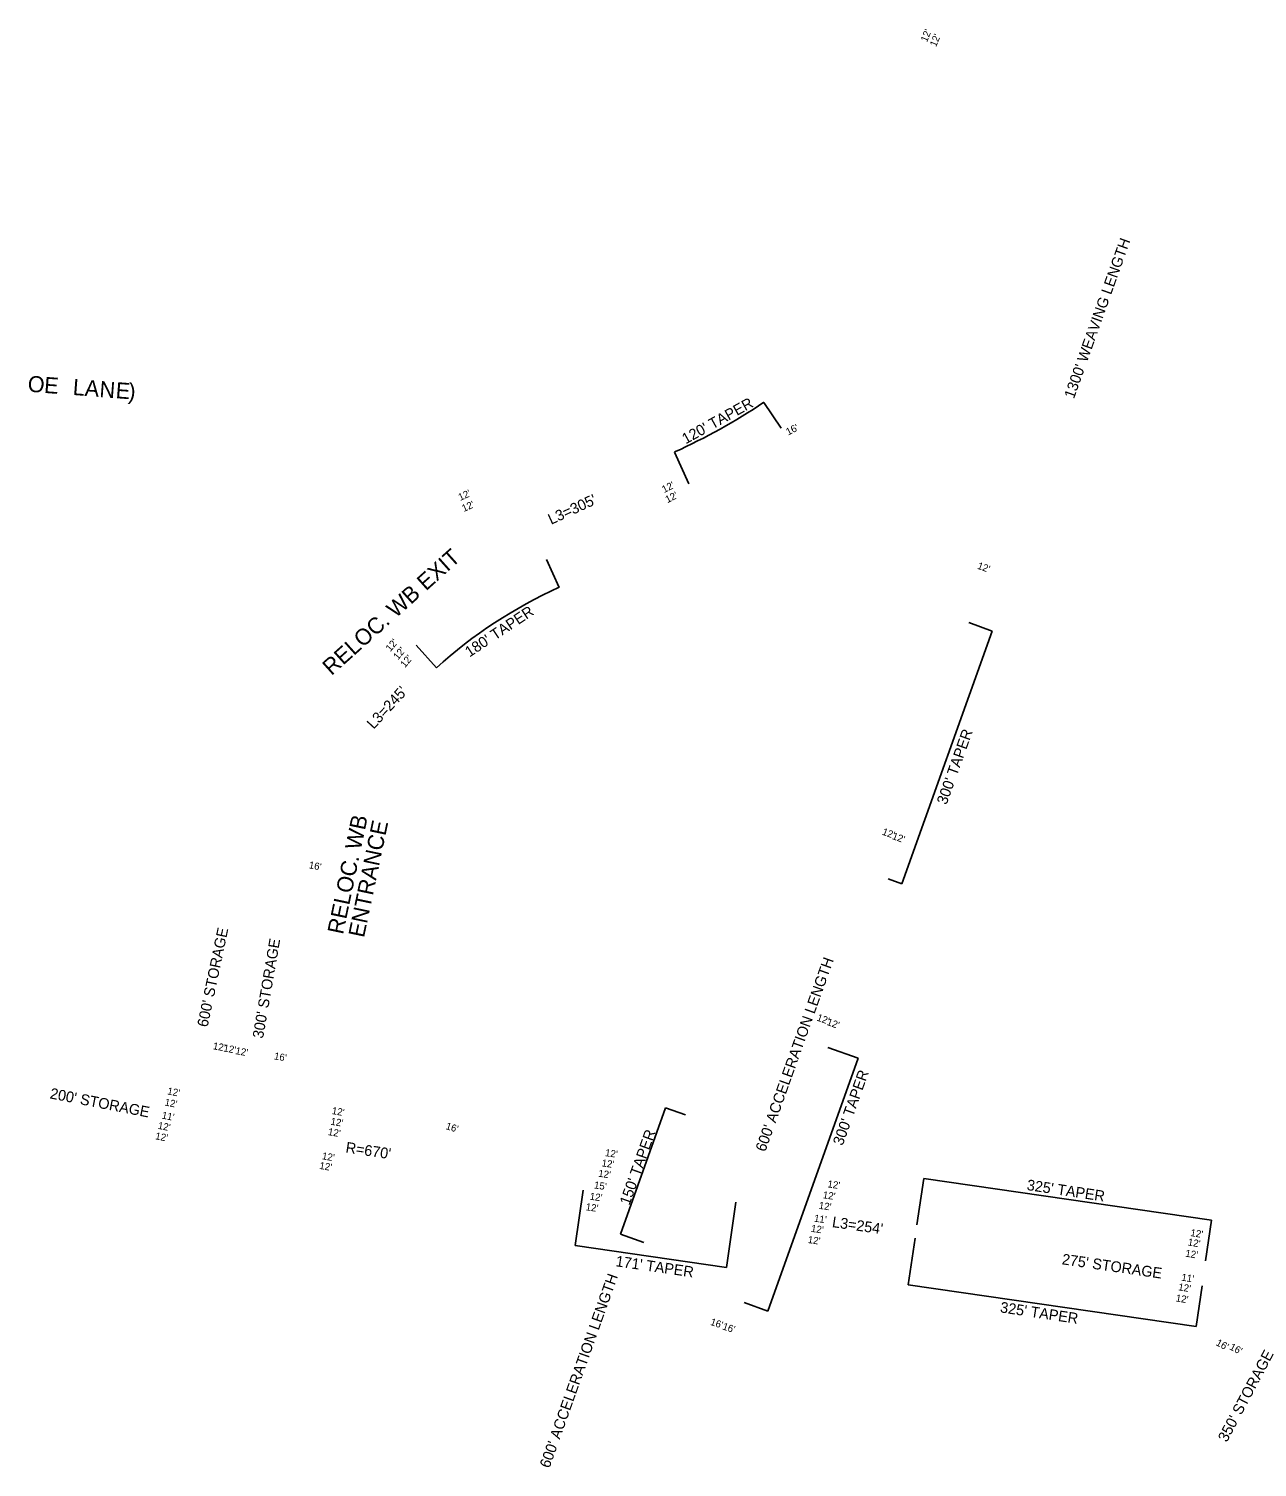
# Model space of a CAD drawing. Extents: x 1938746 to 1943895, y 778846 to 782535.
# Drawn here: x 1940112 to 1941485, y 780080 to 781688 of the extents above; entities that cross this region are included whole.
import ezdxf

# ---------------------------------------------------------------- set-up
doc = ezdxf.new("R2010")
doc.units = 0
for name, color, linetype in [('RD_PD_Final_TX', 7, 'Continuous'), ('RD_Sketch2', 7, 'Continuous'), ('RD_TX_RoadID', 7, 'Continuous')]:
    doc.layers.add(name, color=color, linetype=linetype)

msp = doc.modelspace()

# ---------------------------------------------------------------- linework, layer by layer
at = {"layer": 'RD_PD_Final_TX'}
for p, q in [((1940953.2, 781241.4), (1940933.7, 781270.4)), ((1940850.2, 781179.4), (1940834.1, 781214.9)), ((1940691, 781094.7), (1940705, 781063.7)), ((1941162.8, 781024.3), (1941189.2, 781014.9)), ((1941189.2, 781014.9), (1941088, 780732.5)), ((1940545.1, 780999), (1940567.9, 780973.8)), ((1941072.9, 780737.9), (1941088, 780732.5)), ((1941005.5, 780549.6), (1941039.4, 780537.4)), ((1941039.4, 780537.4), (1940938.2, 780255)), ((1940824.1, 780482.1), (1940773.5, 780340.9)), ((1940846.4, 780474.1), (1940824.1, 780482.1)), ((1940731.8, 780390.2), (1940722.9, 780328.3)), ((1941105, 780351.2), (1941112.6, 780403.2)), ((1941112.6, 780403.2), (1941434.2, 780356.5)), ((1940902.6, 780376.5), (1940892.1, 780303.8)), ((1941427.6, 780311), (1941434.2, 780356.5)), ((1940799.6, 780331.6), (1940773.5, 780340.9)), ((1940722.9, 780328.3), (1940892.1, 780303.8)), ((1941095.3, 780284.4), (1941102.9, 780336.4)), ((1941095.3, 780284.4), (1941417, 780237.8)), ((1941417, 780237.8), (1941423.6, 780283.3)), ((1940911.9, 780264.5), (1940938.2, 780255))]:
    msp.add_line(p, q, dxfattribs=at)
for centre, radius, start, end in [((1940553.4, 781835.6), 681.2, 294.3372, 303.9372), ((1940927.5, 780575), 537, 114.4839, 132.0431)]:
    msp.add_arc(centre, radius, start, end, dxfattribs=at)

# ---------------------------------------------------------------- texts
for s, height, rotation, p in [("12'", 8, 67.2741, (1941116.1, 781672.4)), ("12'", 8, 67.2741, (1941126.3, 781667.1)), ("1300' WEAVING LENGTH", 12, 70.3766, (1941280.4, 781273.7)), ("120' TAPER", 12, 29.024, (1940846.5, 781223.4)), ("16'", 8, 26.6884, (1940961, 781233.3)), ("12'", 8, 26.6884, (1940822.4, 781169)), ("L3=305'", 12, 24.7143, (1940696.1, 781133.5)), ("12'", 8, 26.6884, (1940826.1, 781157.7)), ("12'", 8, 340.2909, (1941171.8, 781084.7)), ("180' TAPER", 12, 33.6891, (1940604.9, 780985.2)), ("12'", 8, 50.0785, (1940516.5, 780991.3)), ("12'", 8, 50.0785, (1940525, 780982.1)), ("12'", 8, 50.0785, (1940532.8, 780973.3)), ("L3=245'", 12, 47.2783, (1940497.7, 780904.5)), ("300' TAPER", 12, 70.3766, (1941138, 780820)), ("12'", 8, 340.2909, (1941065.4, 780787.5)), ("12'", 8, 340.2909, (1941076.6, 780782.6)), ("16'", 8, 349.8498, (1940424.9, 780749.8)), ("600' STORAGE", 12, 78.0869, (1940312.1, 780571.6)), ("300' STORAGE", 12, 80.1542, (1940374.1, 780559)), ("600' ACCELERATION LENGTH", 12, 70.3766, (1940935.4, 780432.2)), ("12'", 8, 340.2909, (1940992.3, 780579.8)), ("12'", 8, 340.2909, (1941003.5, 780574.9)), ("12'", 8, 349.8498, (1940317.7, 780547.6)), ("12'", 8, 349.8498, (1940329.4, 780545.2)), ("12'", 8, 349.8498, (1940342.8, 780542.2)), ("16'", 8, 349.8498, (1940386, 780536.3)), ("300' TAPER", 12, 70.3766, (1941021.9, 780439.1)), ("200' STORAGE", 12, 349.0097, (1940135.3, 780492.7)), ("12'", 8, 348.9507, (1940266.7, 780497.2)), ("12'", 8, 348.9507, (1940263.7, 780484.8)), ("11'", 8, 348.9507, (1940260.5, 780470.2)), ("12'", 8, 350.2755, (1940449.2, 780463.3)), ("12'", 8, 350.2755, (1940450.6, 780475.2)), ("12'", 8, 348.9507, (1940253.2, 780447)), ("12'", 8, 348.9507, (1940256.1, 780458.7)), ("12'", 8, 350.2755, (1940446.3, 780451.7)), ("16'", 8, 342.8619, (1940577.7, 780458.4)), ("150' TAPER", 12, 70.3766, (1940783.6, 780372.5)), ("R=670'", 12, 351.4848, (1940465.9, 780432.2)), ("12'", 8, 350.2755, (1940436.7, 780413.9)), ("12'", 8, 350.2755, (1940439.6, 780424.7)), ("12'", 8, 351.7503, (1940752.2, 780416.8)), ("12'", 8, 351.7503, (1940756, 780428.2)), ("12'", 8, 351.7503, (1940748.4, 780405.2)), ("15'", 8, 351.7503, (1940743.7, 780392.1)), ("12'", 8, 351.7503, (1940999.4, 780381.1)), ("12'", 8, 351.7503, (1941004.6, 780393.3)), ("325' TAPER", 12, 351.4848, (1941227.2, 780390.3)), ("12'", 8, 351.7503, (1940734.4, 780367.7)), ("12'", 8, 351.7503, (1940738.9, 780379.5)), ("12'", 8, 351.7503, (1940994.9, 780369.3)), ("11'", 8, 351.7503, (1940989.6, 780355)), ("L3=254'", 12, 351.7764, (1941009.6, 780348.9)), ("12'", 8, 351.7503, (1940986.2, 780343.6)), ("12'", 8, 350.6045, (1941410.2, 780338.9)), ("12'", 8, 351.7503, (1940982.6, 780331.1)), ("12'", 8, 350.6045, (1941407.3, 780328.4)), ("171' TAPER", 12, 351.7764, (1940767.7, 780305.1)), ("275' STORAGE", 12, 351.7764, (1941266.4, 780307.3)), ("12'", 8, 350.6045, (1941404.5, 780315.9)), ("600' ACCELERATION LENGTH", 12, 70.3766, (1940694.2, 780078.7)), ("11'", 8, 350.6045, (1941400.1, 780289.1)), ("12'", 8, 350.6045, (1941396.6, 780278.3)), ("325' TAPER", 12, 351.4848, (1941197.4, 780253.6)), ("12'", 8, 350.6045, (1941393.8, 780265.9)), ("16'", 8, 342.1523, (1940873.4, 780239.6)), ("16'", 8, 342.1523, (1940887, 780234.6)), ("16'", 8, 332.1494, (1941438.4, 780217.2)), ("350' STORAGE", 12, 62.0851, (1941451.3, 780107.7)), ("16'", 8, 332.1494, (1941453.6, 780212.5))]:
    msp.add_text(s, height=height, rotation=rotation, dxfattribs=at).set_placement(p)
at = {"layer": 'RD_Sketch2'}
for p in [(1940594.5, 781160.2), (1940598.5, 781147.8)]:
    msp.add_text("12'", height=8, rotation=24.4573, dxfattribs=at).set_placement(p)
at = {"layer": 'RD_TX_RoadID'}
for s, rotation, p in [('O', 355.7536, (1940110.7, 781282.4)), ('E', 355.7536, (1940129, 781281)), ('L', 355.7536, (1940161.1, 781278.7)), ('A', 355.7536, (1940174.4, 781277.7)), ('N', 355.7536, (1940190.9, 781276.4)), ('E', 355.7536, (1940209, 781275.1)), (')', 355.7536, (1940223.1, 781274.1)), ('RELOC. WB EXIT', 41.8508, (1940450.6, 780964.5)), ('RELOC. WB ', 78.126, (1940463.5, 780675.1)), ('ENTRANCE', 78.126, (1940486.9, 780671.5))]:
    msp.add_text(s, height=18, rotation=rotation, dxfattribs=at).set_placement(p)

doc.saveas('drawing.dxf')
